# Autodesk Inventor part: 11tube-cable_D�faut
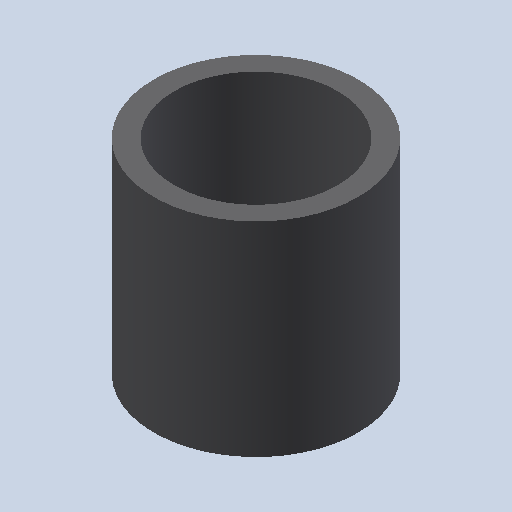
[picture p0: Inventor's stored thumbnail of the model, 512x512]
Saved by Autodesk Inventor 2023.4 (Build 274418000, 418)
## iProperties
Created: 2011-01
Part Number: 11tube-cable_D�faut
Document SubType Name: Modeling
Designer: eric
Density: 1 g/cm^3
Mass: 0.282743 g
Surface Area: 6.22035 cm^2
Volume: 0.282743 cm^3
Material: Générique
Appearance: Red
Author: eric
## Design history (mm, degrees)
feature "Base1"
node "Corps solides"
node "Corps surfaciques"
node "Solide1"
